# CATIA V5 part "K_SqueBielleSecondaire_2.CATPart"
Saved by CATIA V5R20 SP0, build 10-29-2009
Part number: Squelette_bielle_secondaire_2
Publications: "Plan_bielle_secondaire", "Axe_pivot_bielle_secondaire_1'", "Axe_pivot_bielle_secondaire_2'", "Droite_bielle_secondaire_2"
Bounding box of the stored display mesh (mm): x -399.988 to 0, y 10 to 50, z -150 to -146.894
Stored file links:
  G:\Khaled_CFAO_2011\ST2M\ST2M_GR2\jcoetard\Khaled\CAD_CATIA\K_SqueBielleSecondaire_2.CATPart
  G:\Khaled_CFAO_2011\ST2M\ST2M_GR2\jcoetard\jcoetard\Maquette_jcoetard\Squelette_bielle_motrice_2.CATPart
  G:\Khaled_CFAO_2011\ST2M\ST2M_GR2\jcoetard\Khaled\CAD_CATIA\K_Squelette.CATProduct
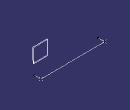
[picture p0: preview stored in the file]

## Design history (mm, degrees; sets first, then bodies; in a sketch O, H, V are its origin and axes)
Set1
  Point1: linked copy from another document
  Point2 "Point.9": linked copy from another document
  Plane1 "Plan_Ref": linked copy from another document
Set2 "Set géométrique"
  Plane2 "Plan_bielle_secondaire": type Offset, RefPlane Plane1, Offset 5, reversed
  Line1 "Axe_pivot_bielle_secondaire_1'": type Normal, RefPoint Point1, RefSkin Plane2, Start 0, End 40
  Line2 "Axe_pivot_bielle_secondaire_2'": type Normal, RefPoint Point2, RefSkin Plane2, Start 0, End 40
  Line3 "Droite_bielle_secondaire_2": type PtPt, FirstPoint Point1, SecondPoint Point2
Body1 (main body)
